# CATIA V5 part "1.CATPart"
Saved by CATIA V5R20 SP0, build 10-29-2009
Part number: Part1
Material "Steel": density 7860 kg/m3, Young's modulus 2e+11 Pa, Poisson ratio 0.266, thermal expansion 1.17e-05 1/K
Bounding box of the stored display mesh (mm): x -85 to 85, y -85 to 85, z -4 to 11.032
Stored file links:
  E:\Ehsan\Amoozesh\CATIA\CATIA Course\Advanced\Videos\Session-16\1.CATPart
  D:\CATIA V5R20\B20\intel_a\startup\materials\Catalog.CATMaterial
  D:\CATIA V5R20\B20\intel_a\resources\graphic\figures\CATIA_EnvironmentMap_Satin_512x512.jpg
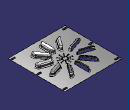
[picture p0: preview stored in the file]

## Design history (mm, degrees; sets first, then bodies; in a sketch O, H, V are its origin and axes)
SheetMetalParameters1: Thickness 0.5, BendRadius 1, KFactor 0.400515 {= log(min(100,max(20*SheetMetalParameters1.BendRadius,SheetMetalParameters1.Thickness)/SheetMetalParameters1.Thickness))/log(100)/2}, ReliefRadialLength 1, ReliefAxialLength 2, MinimumBendRadius 0
AxisSystem1: origin (0, 0, 0), X (1, 0, 0), Y (0, 1, 0), Z (0, 0, 1)
Body1 (main body), material "Steel"
  Sketch1 on xy-plane, origin (0, 0, 0), H (1, 0, 0), V (0, 1, 0)
    line L1 (85, 85) -> (85, -85)
    line L2 (85, -85) -> (-85, -85)
    line L3 (-85, -85) -> (-85, 85)
    line L4 (-85, 85) -> (85, 85)
    distance L2 L4 = 170
    distance L1 L3 = 170
    vertical: L1 V, L3 V
    horizontal: L2 H, L4 H
    equidistance: L1 L3 O, L2 L4 O
  Wall1: Thickness 0.5, Profile Sketch1
  d_Stamp1: NewRoot_AttribNormalisation "No Standard", Stamp_FilletRadius 2, Stamp_IntersectFilletRadius 2
  SHM_CircPattern1: RadialStep 20, Direction edge [ZX plane of AxisSystem1 | YZ plane of AxisSystem1], Item d_Stamp1, RadialNumber 1, AngularNumber 10, AngularPosition 1, RadialPosition 1, AngleXY 0, AngularStep 36 {= 360.0*1 deg/SHM_CircPattern1.AngularNumber}
  CutOut1: Direction Sketch3, EndLimit through (limit type 2), Orientation true, Profile Sketch3, StartLimit through (limit type 2)
  SHM_CircPattern2: RadialStep 5, Direction edge [ZX plane of AxisSystem1 | YZ plane of AxisSystem1], Item CutOut1, RadialNumber 3, AngularNumber 10, AngularPosition 1, RadialPosition 1, AngleXY 0, AngularStep 36
  Sketch2 on face of Wall1, origin (76.4896, -2.091, 0.5), H (1, 0, 0), V (0, 1, 0)
    point P1 (0.5104, 2.091)
    reference projected line E1 through (0, 2.091) direction (1, 0) from edge [XY plane of AxisSystem1 | ZX plane of AxisSystem1]
    reference projected line E2 (8.5104, 87.091) -> (8.5104, -82.909) from edge [face of Wall1 | face of Wall1]
    distance P1 E2 = 8
    coincidence: P1 E1
  d_Stamp2: NewRoot_AttribNormalisation "No Standard", Stamp_FilletRadius 0.5, Stamp_IntersectFilletRadius 2
  RectPattern1: of d_Stamp2, direction 1 instances 3, spacing 77.5, along edge [face of Wall1 | face of Wall1], direction 2 instances 3, spacing 77, along edge [face of Wall1 | face of Wall1] reversed, Nu 2
  Sketch3 on face of Wall1, origin (0, 0, 0.5), H (1, 0, 0), V (0, 1, 0)
    circle A1 centre (0, -7) radius 1.5
    point P1 (0, -7)
    distance P1 H = 7
    radius A1 = 1.5
    coincidence: P1 V
  Sketch4 on face of Wall1, origin (0, 0, 0.5), H (1, 0, 0), V (0, 1, 0)
    construction line L1 (0, -37.5) -> (0, -62.5)
    line L2 (7.5, -62.5) -> (7.5, -37.5)
    arc A1 centre (0, -62.5) radius 7.5 from (0, -70) to (7.5, -62.5) ccw
    arc A2 centre (0, -37.5) radius 7.5 from (7.5, -37.5) to (0, -30) ccw
    line L3 (0, -70) -> (0, -30)
    point P5 (0, -70)
    point P6 (0, -30)
    distance A2 A1 = 40
    distance L2 L3 = 7.5
    distance P6 H = 30
    radius A2 = 7.5
    vertical: L1 V, L3 V
    tangency: A1 L2, A2 L2
    coincidence: P5 V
